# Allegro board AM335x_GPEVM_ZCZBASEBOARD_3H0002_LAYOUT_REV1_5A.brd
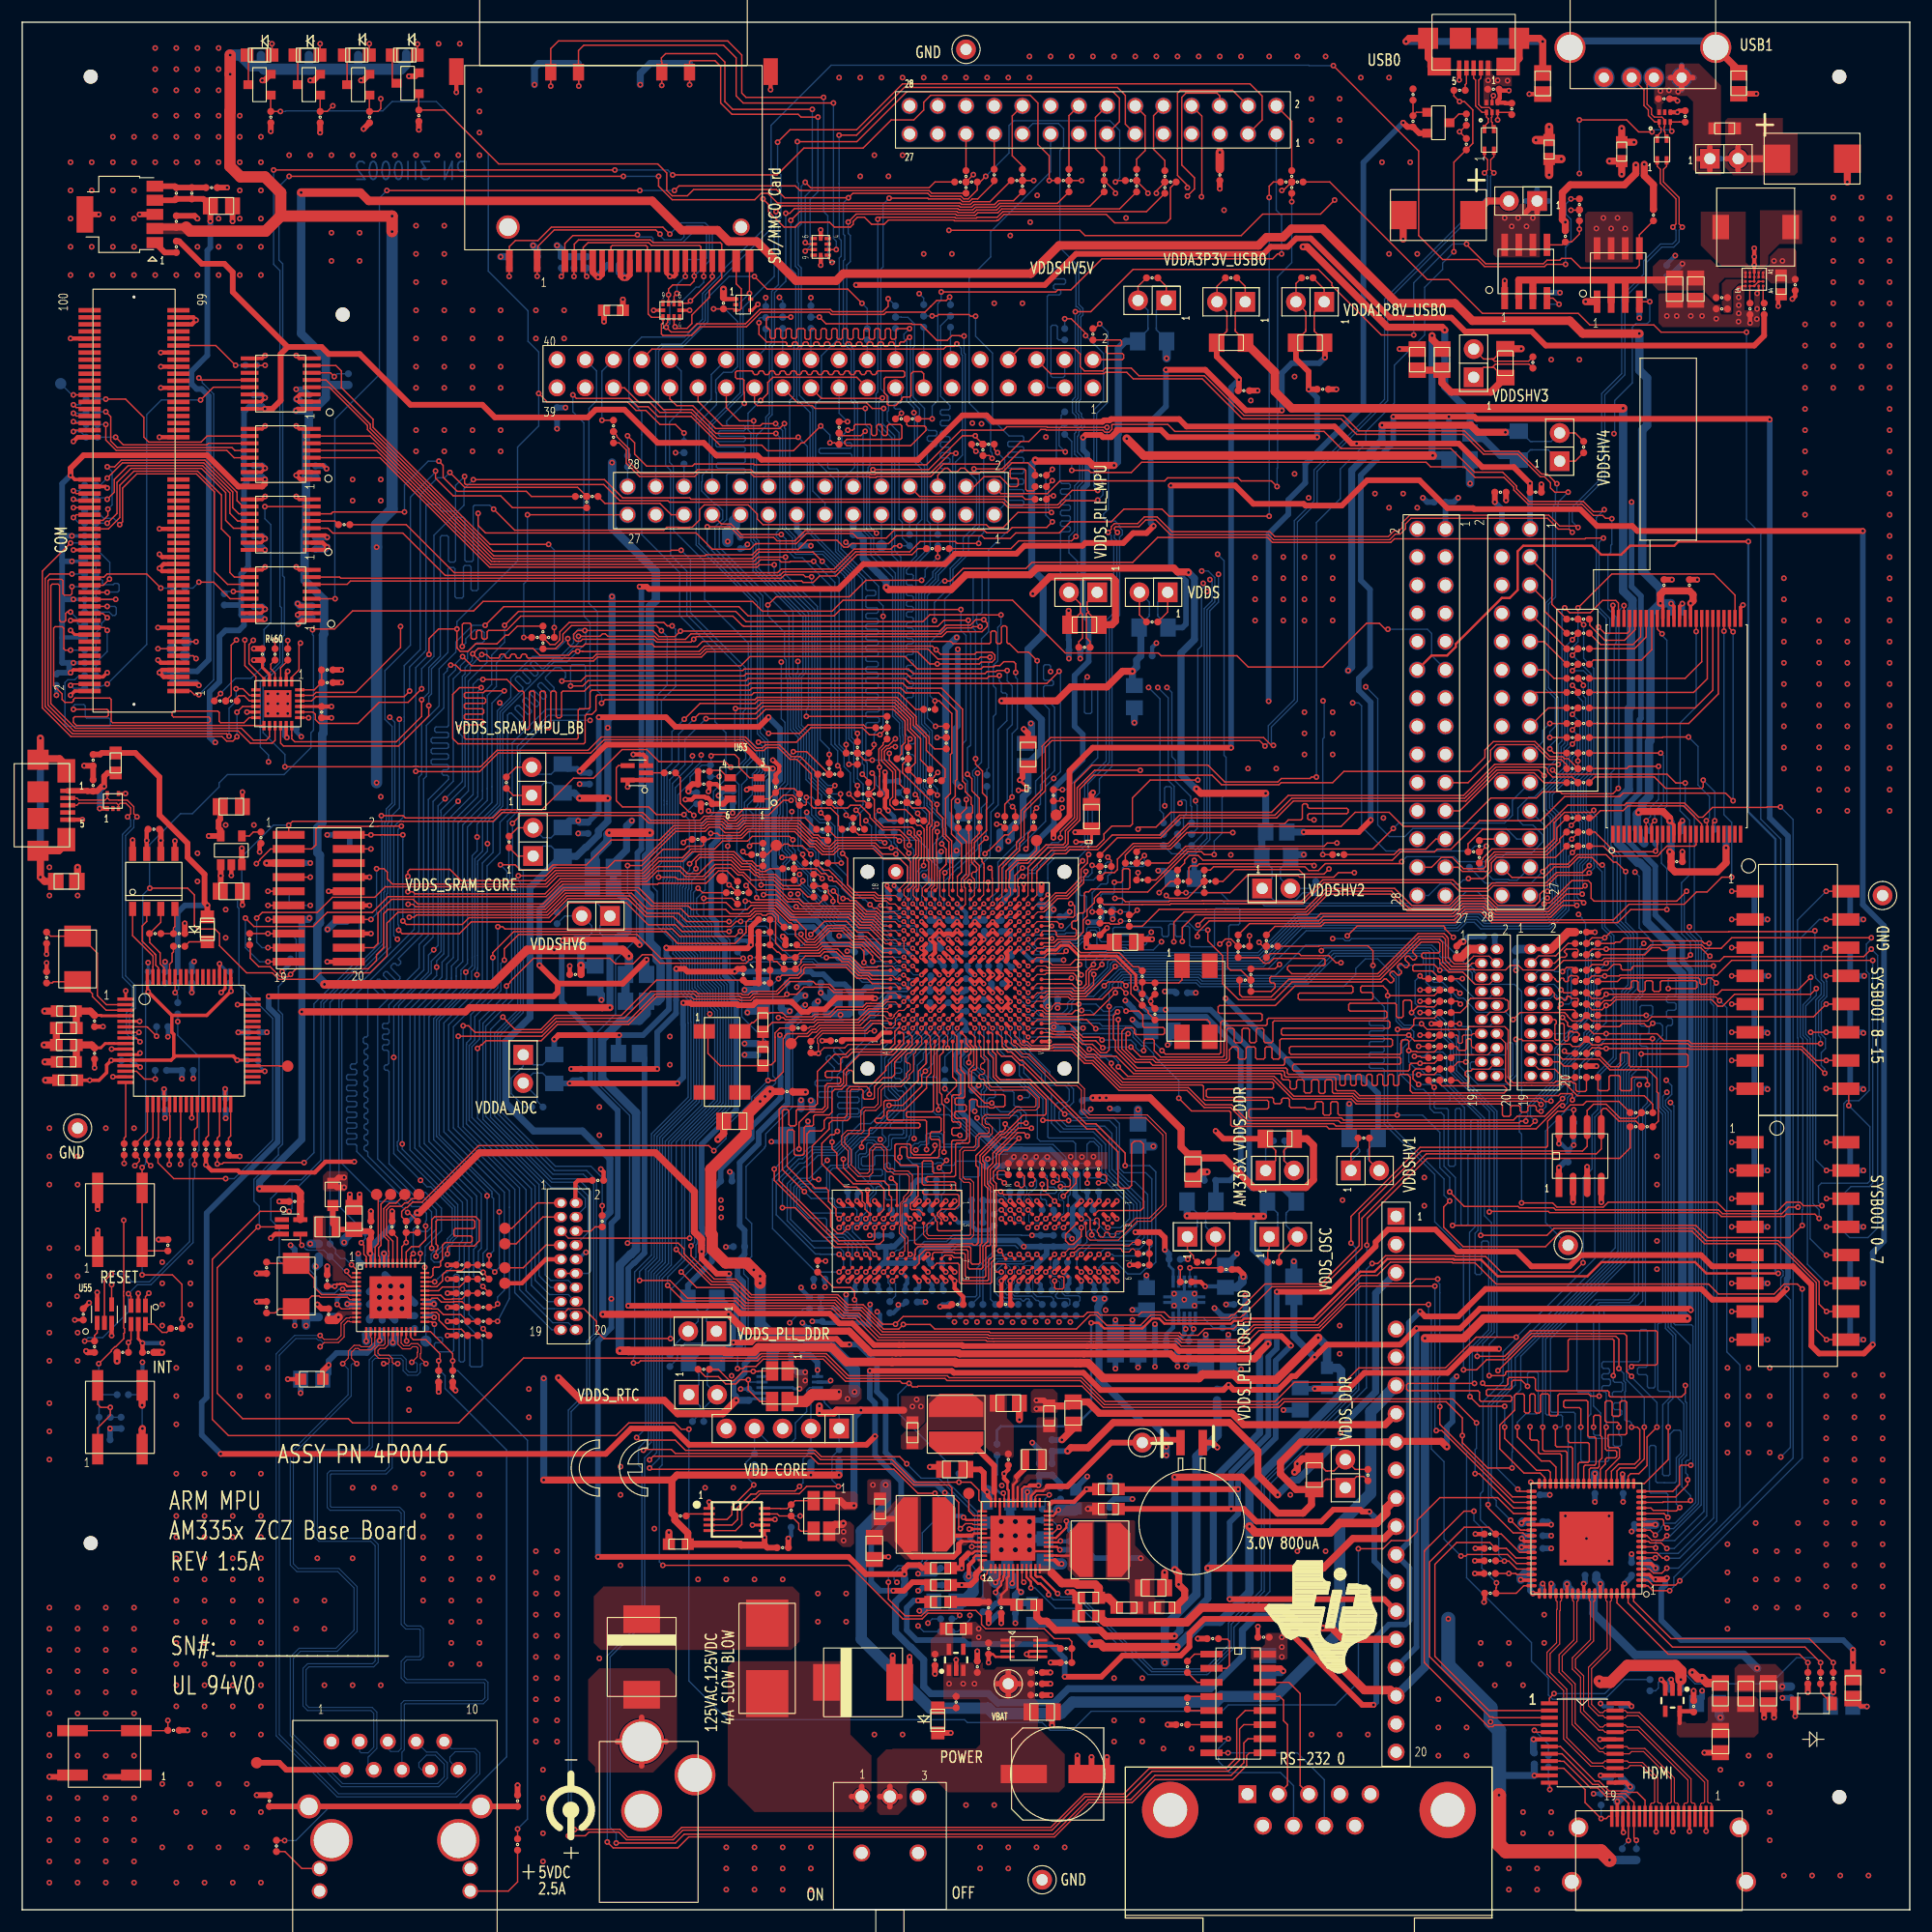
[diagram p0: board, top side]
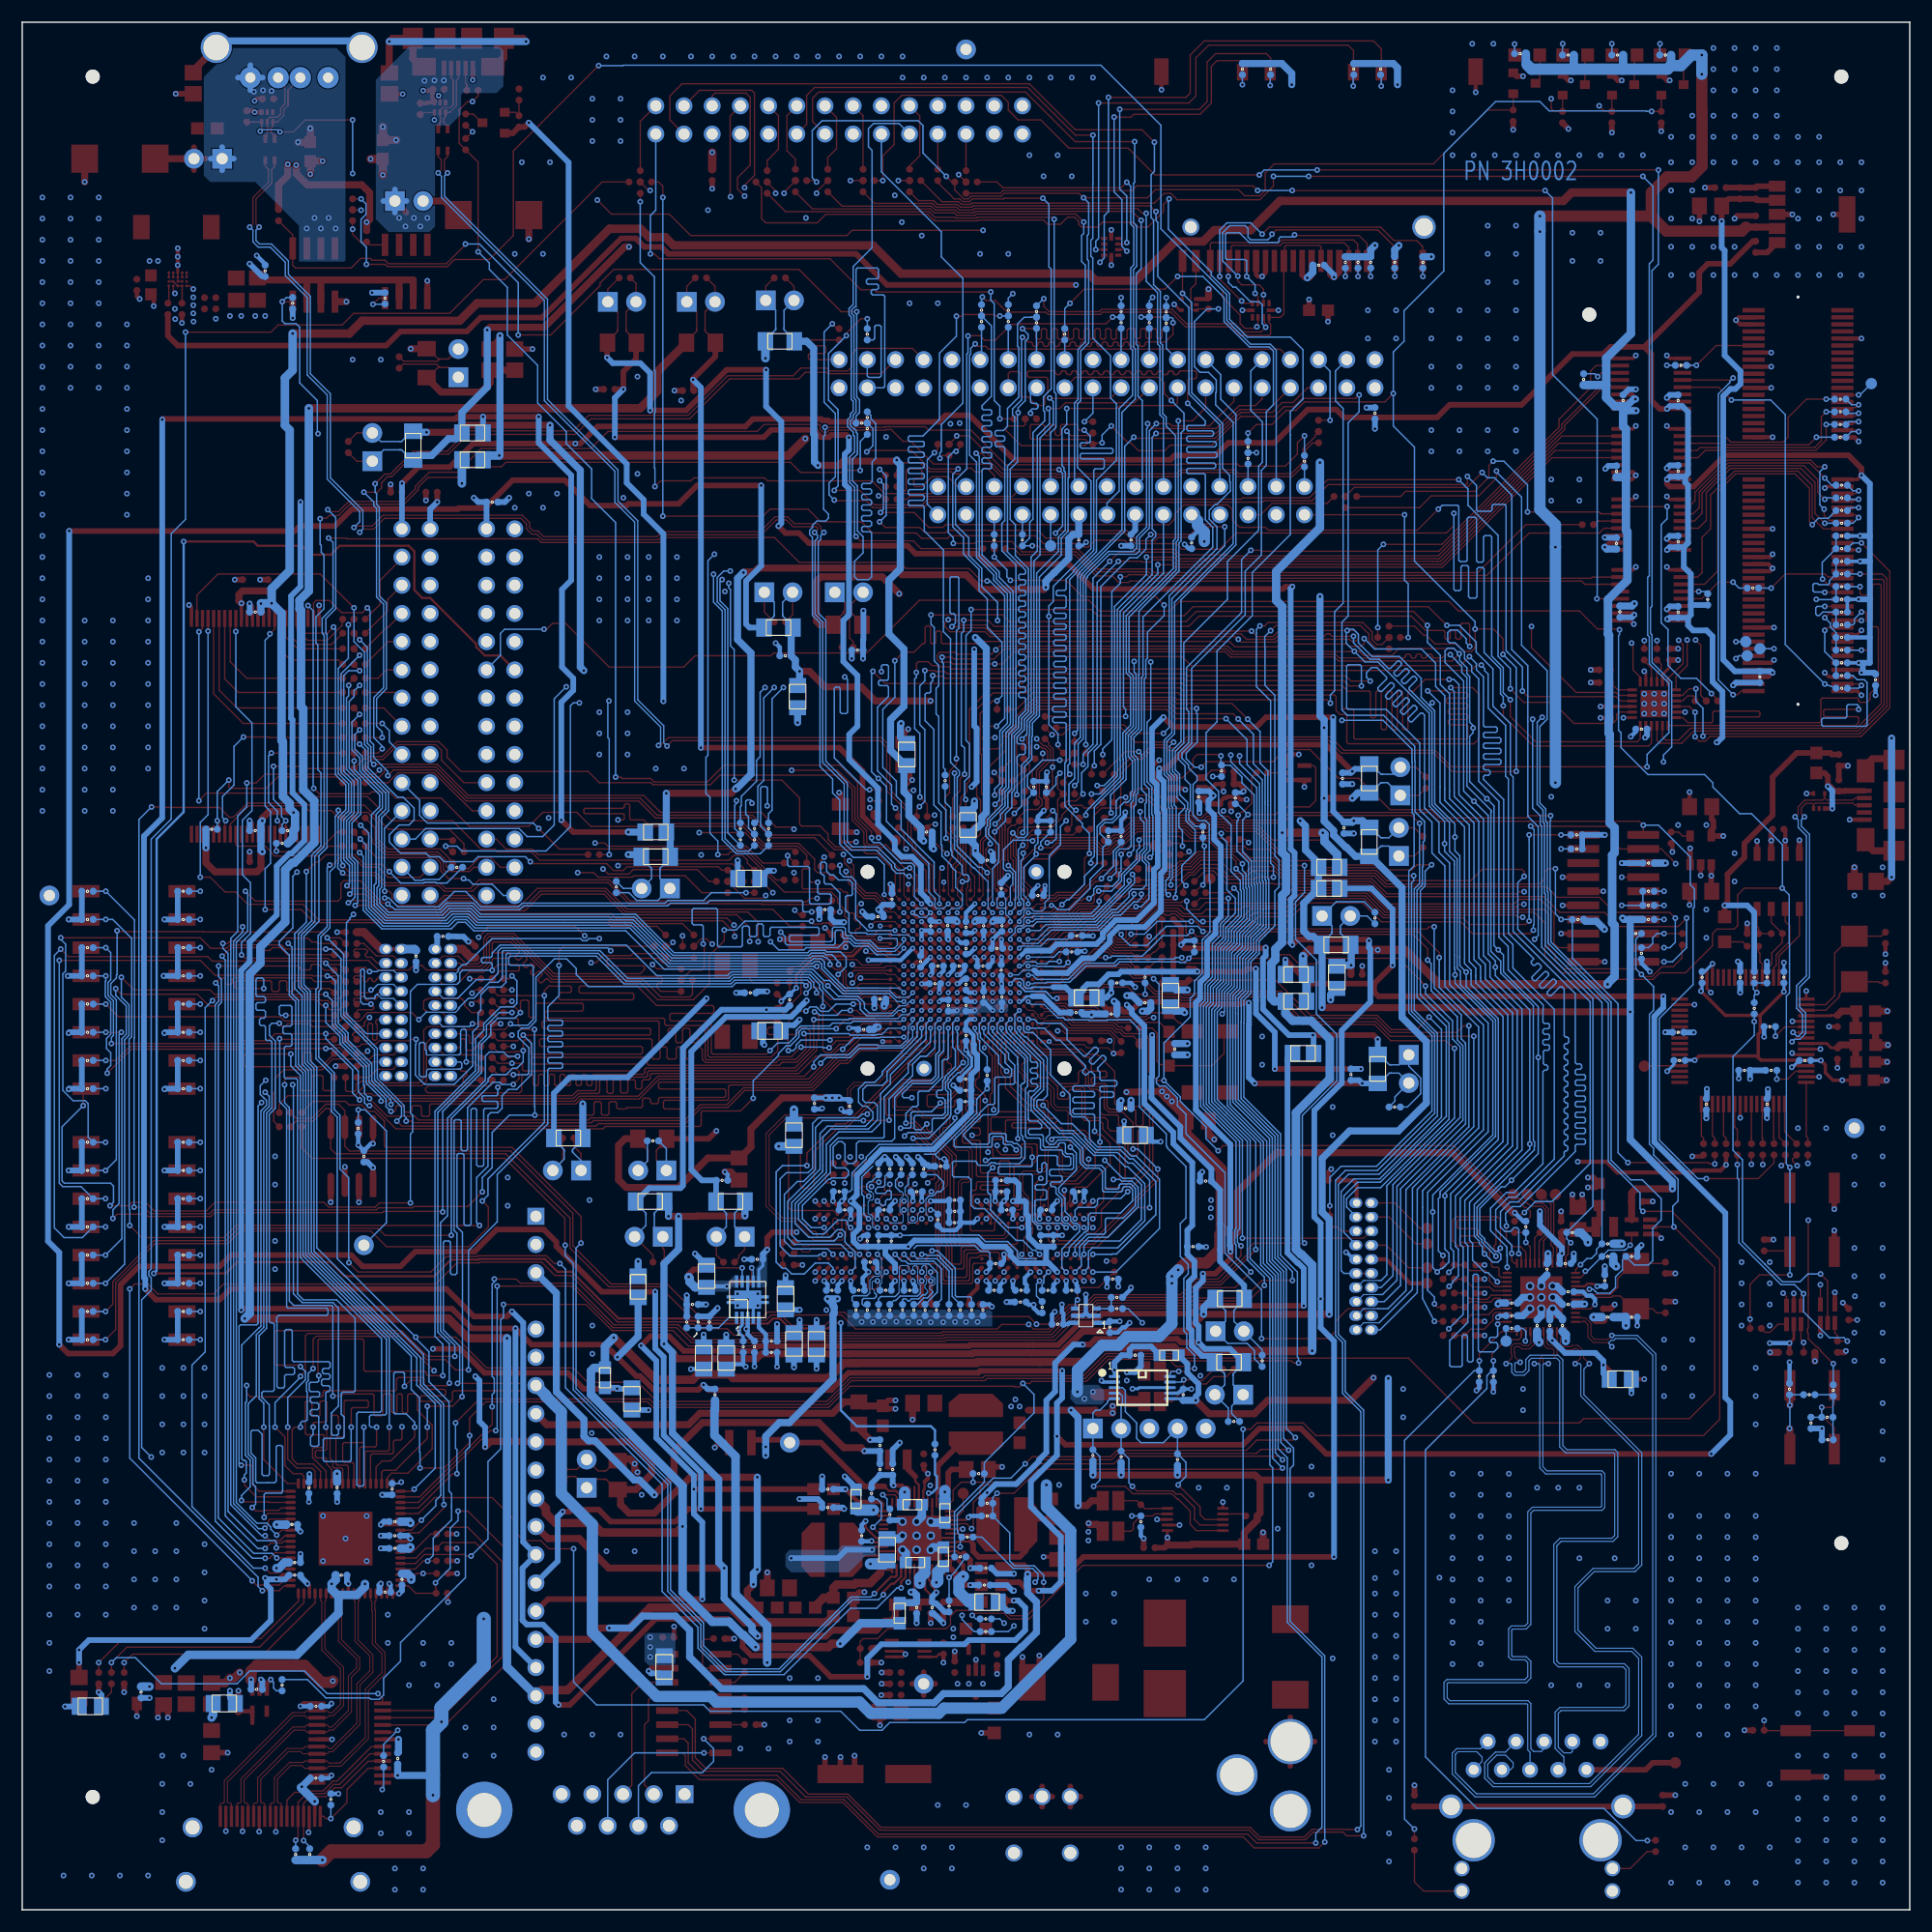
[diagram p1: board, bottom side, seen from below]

Outline 170 x 170 mm; copper layers: TOP, LY2_GND, LY3, LY4, LY5_GND, BOTTOM. Coordinates in mm from the lower left corner of the outline.
Outline path: 0,170 170,170 170,0 0,0 0,170

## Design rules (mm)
net group DDR_DQS0: nets DDR_DQS0 DDR_DQSN0
net group DDR_DQS1: nets DDR_DQS1 DDR_DQSN1
net group EMU_USB: nets EMU_USB_DM EMU_USB_DP
net group ETHER_D0: nets ETHER_D0N ETHER_D0P
net group ETHER_D1: nets ETHER_D1N ETHER_D1P
net group ETHER_D2: nets ETHER_D2N ETHER_D2P
net group ETHER_D3: nets ETHER_D3N ETHER_D3P
net group JTAG: nets JTAG_TDI JTAG_TDO
net group USB1: nets USB1_DM USB1_DP
net group 54: nets AM335X_LCD_DATA0 AM335X_LCD_DATA1 AM335X_LCD_DATA2 AM335X_LCD_DATA3 AM335X_LCD_DATA4 AM335X_LCD_DATA5 AM335X_LCD_DATA6 AM335X_LCD_DATA7 AM335X_LCD_DATA8 AM335X_LCD_DATA9 AM335X_LCD_DATA10 AM335X_LCD_DATA11 AM335X_LCD_DATA12 AM335X_LCD_DATA13 AM335X_LCD_DATA14 AM335X_LCD_DATA15 HDMI_D0 HDMI_D1 HDMI_D2 HDMI_D3 HDMI_D4 HDMI_D5 HDMI_D6 HDMI_D7 HDMI_D8 HDMI_D9 HDMI_D10 HDMI_D11 HDMI_D12 HDMI_D13 HDMI_D14 HDMI_D15 HDMI_D17 HDMI_D18 HDMI_D19 HDMI_D20 HDMI_D21 HDMI_D22 HDMI_D23 HDMI_DE
net group 69: nets AM335X_GMII1_RXD3 ETH_REFCLK ETH_RXCLK ETH_RXD0 ETH_RXD1 ETH_RXD2 ETH_RXD3 ETH_RXDV ETH_TXCLK ETH_TXD0 ETH_TXD1 ETH_TXD2 ETH_TXD3 ETH_TXEN
net group 78: nets AM335X_GMII1_REFCLK
net group 80: nets AM335X_GPMC_A1 AM335X_GPMC_A2 AM335X_GPMC_A3 AM335X_GPMC_BE1N AM335X_GPMC_CLK AM335X_GPMC_CS3N AM335X_MMC2_CLK AM335X_MMC2_CMD AM335X_MMC2_D0 AM335X_MMC2_D1 AM335X_MMC2_D2 AM335X_MMC2_D3 MMC2_CLK MMC2_CMD MMC2_D0 MMC2_D1 MMC2_D2 MMC2_D3
net group 81: nets EXP_GPMC_BE1N EXP_GPMC_CLK EXP_GPMC_CS3N GPMC_A1 GPMC_A2 GPMC_A3 SDIO_GPMC_A1 SDIO_GPMC_A2 SDIO_GPMC_A3 SDIO_GPMC_BE1N SDIO_GPMC_CLK SDIO_GPMC_CS3N
net group DLP-RGB: nets HDMI_HSYNC HDMI_PCLK HDMI_VSYNC
net group EXP_MMC0: nets EXP_MMC0_CLK EXP_MMC0_CMD EXP_MMC0_DAT0 EXP_MMC0_DAT1 EXP_MMC0_DAT2 EXP_MMC0_DAT3
net group H_SDMMC2: nets EXP_MMC1_CLK EXP_MMC1_CMD EXP_MMC1_DAT0 EXP_MMC1_DAT1 EXP_MMC1_DAT2 EXP_MMC1_DAT3 EXP_MMC1_DAT4 EXP_MMC1_DAT5 EXP_MMC1_DAT6 EXP_MMC1_DAT7
net group POWER_TRACE: nets VDDSHV1
net group SD_MMC_CC: nets MMC_CLK MMC_CMD MMC_D0 MMC_D1 MMC_D2 MMC_D3 MMC_D4 MMC_D5 MMC_D6 MMC_D7
net group USB: nets USB0_CONN_DM USB0_CONN_DP USB0_DM USB0_DP USB1_CONN_DM USB1_CONN_DP
nets with their own width: min track width 0.381; nets VDDSHV4 VDDSHV6
nets with their own width: min track width 0.508; nets VDDR_VTT

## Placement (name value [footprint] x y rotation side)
BT1  CoinBattery3.1V  [MS920SE-FL27E]  105.32 42.07 90 top
C1  0.01uF  [SM-7351-CAP-0402]  64.05 100.24 270 bottom
C2  25pF  [SM-7351-CAP-0603]  66.71 79.92 90 top
C3  25pF  [SM-7351-CAP-0603]  66.71 76.87 270 top
C4  18pF  [SM-7351-CAP-0402]  102.02 80.66 90 top
C5  18pF  [SM-7351-CAP-0402]  102.02 82.97 270 top
C6  0.01uF  [SM-7351-CAP-0402]  61.38 101.38 180 top
C7  0.01uF  [SM-7351-CAP-0402]  61.38 102.53 180 top
C8  0.01uF  [SM-7351-CAP-0402]  61.63 99.61 180 top
C9  0.1uF  [SM-7351-CAP-0402]  68.62 85.25 270 top
C10  0.001uF  [SM-7351-CAP-0402]  69.63 85.25 270 top
C11  0.1uF  [SM-7351-CAP-0402]  66.84 86.91 180 top
C12  0.001uF  [SM-7351-CAP-0402]  66.84 88.05 180 top
C13  0.1uF  [SM-7351-CAP-0402]  66.84 84.62 180 top
C14  0.001uF  [SM-7351-CAP-0402]  66.84 85.76 180 top
C15  0.01uF  [SM-7351-CAP-0402]  26.96 107.86 270 top
C16  0.01uF  [SM-7351-CAP-0402]  66.2 77.51 90 bottom
C17  0.01uF  [SM-7351-CAP-0402]  68.87 73.7 0 top
C18  0.01uF  [SM-7351-CAP-0402]  76.75 52.74 0 bottom
C19  0.01uF  [SM-7351-CAP-0402]  83.48 85 0 bottom
C20  0.01uF  [SM-7351-CAP-0402]  72.05 52.49 270 bottom
C23  0.01uF  [SM-7351-CAP-0402]  70.65 72.17 0 bottom
C24  0.01uF  [SM-7351-CAP-0402]  85 83.35 270 bottom
C25  0.01uF  [SM-7351-CAP-0402]  92.75 82.02 0 bottom
C27  0.01uF  [SM-7351-CAP-0402]  81.76 88.62 270 bottom
C28  0.01uF  [SM-7351-CAP-0402]  49.82 84.24 180 top
C29  0.01uF  [SM-7351-CAP-0402]  94.21 79.29 0 bottom
C30  0.01uF  [SM-7351-CAP-0402]  71.41 83.48 0 bottom
C31  0.01uF  [SM-7351-CAP-0402]  87.79 83.41 180 bottom
C32  0.01uF  [SM-7351-CAP-0402]  104.43 82.59 0 bottom
C34  0.01uF  [SM-7351-CAP-0402]  85 86.59 270 bottom
C35  0.01uF  [SM-7351-CAP-0402]  85.64 85 180 bottom
C36  0.01uF  [SM-7351-CAP-0402]  87.54 85 180 bottom
C41  0.01uF  [SM-7351-CAP-0402]  82.21 86.59 0 bottom
C42  0.01uF  [SM-7351-CAP-0402]  83.41 88.62 270 bottom
C43  0.01uF  [SM-7351-CAP-0402]  83.1 94.53 180 bottom
C45  0.01uF  [SM-7351-CAP-0402]  88.56 97.07 180 bottom
C46  0.01uF  [SM-7351-CAP-0402]  86.65 88.63 270 bottom
C47  0.01uF  [SM-7351-CAP-0402]  78.52 91.35 180 bottom
C48  0.01uF  [SM-7351-CAP-0402]  91.67 91.03 90 bottom
C50  0.01uF  [SM-7351-CAP-0402]  92.94 89.45 0 bottom
C52  0.01uF  [SM-7351-CAP-0402]  68.87 81.7 180 bottom
C53  0.01uF  [SM-7351-CAP-0402]  81.83 84.62 270 bottom
C56  0.01uF  [SM-7351-CAP-0402]  71.92 80.68 0 bottom
C60  1uF  [SM-7351-CAP-0402]  69.25 86.91 180 top
C61  0.01uF  [SM-7351-CAP-0402]  117.13 136.94 0 top
C62  0.01uF  [SM-7351-CAP-0402]  110.02 136.82 0 top
C63  0.01uF  [SM-7351-CAP-0402]  50.33 75.22 90 bottom
C64  0.01uF  [SM-7351-CAP-0402]  106.97 65.7 180 bottom
C65  1uF  [SM-7351-CAP-0402]  75.09 80.81 180 bottom
C66  0.01uF  [SM-7351-CAP-0402]  64.55 59.73 180 bottom
C67  0.01uF  [SM-7351-CAP-0402]  100.88 81.95 90 bottom
C68  0.01uF  [SM-7351-CAP-0402]  51.09 101.89 270 bottom
C69  0.01uF  [SM-7351-CAP-0402]  50.96 97.45 270 bottom
C70  0.01uF  [SM-7351-CAP-0402]  94.78 113.45 0 bottom
C71  1uF  [SM-7351-CAP-0402]  75.03 87.73 180 bottom
C72  1uF  [SM-7351-CAP-0402]  75.48 86.27 180 bottom
C73  0.01uF  [SM-7351-CAP-0402]  63.41 65.63 0 bottom
C74  0.01uF  [SM-7351-CAP-0402]  21.63 113.07 90 top
C76  0.01uF  [SM-7351-CAP-0402]  83.41 82.21 90 bottom
C77  0.01uF  [SM-7351-CAP-0402]  81.76 82.21 90 bottom
C78  0.01uF  [SM-7351-CAP-0402]  86.59 81.44 90 bottom
C79  0.01uF  [SM-7351-CAP-0402]  85 81.44 90 bottom
C80  0.01uF  [SM-7351-CAP-0402]  95.48 72.36 270 bottom
C82  0.01uF  [SM-7351-CAP-0402]  98.65 72.62 270 bottom
C83  0.01uF  [SM-7351-CAP-0402]  85 88.49 90 bottom
C84  100uF  [SM-7351-CAP-SMDCAN]  93.26 12.23 180 top
C85  0.1uF  [SM-7351-CAP-0402]  91.35 20.36 0 top
C86  0.1uF  [SM-7351-CAP-0402]  91.35 21.37 0 top
C87  0.01uF  [SM-7351-CAP-0402]  24.17 106.34 0 bottom
C88  1uF  [SM-7351-CAP-0402]  91.35 19.34 0 top
C89  0.01uF  [SM-7351-CAP-0402]  101.26 112.94 0 bottom
C90  0.01uF  [SM-7351-CAP-0402]  89.09 85.41 270 bottom
C91  2.2uF  [SM-7351-CAP-0402]  92.75 41.82 90 bottom
C92  0.01uF  [SM-7351-CAP-0402]  96.56 87.79 0 top
C93  0.01uF  [SM-7351-CAP-0402]  97.7 90.08 0 bottom
C94  0.01uF  [SM-7351-CAP-0402]  88.18 88.61 90 bottom
C96  0.01uF  [SM-7351-CAP-0402]  81.83 91.99 90 bottom
C97  2.2uF  [SM-7351-CAP-0402]  91.6 39.66 90 bottom
C98  0.01uF  [SM-7351-CAP-0402]  94.4 33.69 270 bottom
C101  2.2uF  [SM-7351-CAP-0402]  97.45 36.23 0 bottom
C102  2.2uF  [SM-7351-CAP-0402]  97.45 37.88 0 bottom
C103  2.2uF  [SM-7351-CAP-0402]  88.18 27.22 270 top
C104  2.2uF  [SM-7351-CAP-0402]  89.45 27.22 270 bottom
C107  2.2uF  [SM-7351-CAP-0402]  87.03 27.22 270 top
C108  2.2uF  [SM-7351-CAP-0402]  88.05 27.22 270 bottom
C109  2.2uF  [SM-7351-CAP-0402]  83.22 30.77 180 bottom
C110  2.2uF  [SM-7351-CAP-0402]  83.35 29.25 180 bottom
C111  0.01uF  [SM-7351-CAP-0402]  87.03 23.53 270 top
C112  1uF  [SM-7351-CAP-0402]  86.02 21.88 90 top
C113  1uF  [SM-7351-CAP-0402]  82.21 22.52 270 top
C114  0.01uF  [SM-7351-CAP-0402]  94.02 22.26 180 top
C115  0.01uF  [SM-7351-CAP-0402]  23.53 94.27 0 bottom
C116  0.01uF  [SM-7351-CAP-0402]  139.23 67.86 270 bottom
C117  1uF  [SM-7351-CAP-0402]  13.12 59.85 90 top
C118  1uF  [SM-7351-CAP-0402]  7.4 42.33 0 bottom
C125  0.01uF  [SM-7351-CAP-0402]  80.1 54.74 0 bottom
C126  0.01uF  [SM-7351-CAP-0402]  82.33 58.2 0 bottom
C127  0.1uF  [SM-7351-CAP-0402]  149.01 97.19 0 bottom
C128  0.01uF  [SM-7351-CAP-0402]  149.01 94.4 0 top
C129  0.01uF  [SM-7351-CAP-0402]  149.01 116.88 0 bottom
C130  0.01uF  [SM-7351-CAP-0402]  150.15 119.29 90 top
C131  0.1uF  [SM-7351-CAP-0402]  147.87 119.29 90 top
C132  0.1uF  [SM-7351-CAP-0402]  133.13 127.67 0 top
C133  0.1uF  [SM-7351-CAP-0402]  136.31 127.67 0 top
C134  0.1uF  [SM-7351-CAP-0402]  70.14 123.35 270 bottom
C135  0.1uF  [SM-7351-CAP-0402]  48.17 134.78 270 bottom
C136  0.01uF  [SM-7351-CAP-0402]  134.53 85.89 270 bottom
C137  0.01uF  [SM-7351-CAP-0402]  140.37 88.05 0 top
C138  0.01uF  [SM-7351-CAP-0402]  132.12 87.67 180 bottom
C139  0.01uF  [SM-7351-CAP-0402]  129.2 86.27 90 top
C140  0.01uF  [SM-7351-CAP-0402]  51.85 65.7 0 top
C141  0.1uF  [SM-7351-CAP-0402]  64.68 123.1 270 bottom
C142  0.1uF  [SM-7351-CAP-0402]  145.71 34.71 180 bottom
C143  0.1uF  [SM-7351-CAP-0402]  145.45 31.28 180 bottom
C144  0.1uF  [SM-7351-CAP-0402]  141.64 38.01 270 bottom
C145  0.1uF  [SM-7351-CAP-0402]  136.44 34.96 0 bottom
C146  0.1uF  [SM-7351-CAP-0402]  136.44 32.55 0 bottom
C147  0.1uF  [SM-7351-CAP-0402]  135.8 29.76 270 bottom
C148  0.1uF  [SM-7351-CAP-0402]  74.84 123.35 270 bottom
C149  0.01uF  [SM-7351-CAP-0402]  143.55 18.33 180 bottom
C150  0.1uF  [SM-7351-CAP-0402]  136.44 33.69 0 bottom
C151  0.1uF  [SM-7351-CAP-0402]  145.45 30.14 180 bottom
C152  0.1uF  [SM-7351-CAP-0402]  144.18 38.01 270 bottom
C153  0.1uF  [SM-7351-CAP-0402]  159.3 19.6 270 bottom
C154  0.1uF  [SM-7351-CAP-0402]  141.26 30.14 180 bottom
C155  0.01uF  [SM-7351-CAP-0402]  82.46 55.79 180 bottom
C156  0.01uF  [SM-7351-CAP-0402]  95.92 63.03 0 bottom
C157  0.01uF  [SM-7351-CAP-0402]  136.18 13.63 90 bottom
C158  0.01uF  [SM-7351-CAP-0402]  143.55 11.85 180 bottom
C159  1uF  [SM-7351-CAP-0402]  150.53 18.33 90 top
C160  1uF  [SM-7351-CAP-0402]  148.88 19.85 180 bottom
C161  0.01uF  [SM-7351-CAP-0402]  13.5 111.04 270 bottom
C162  0.01uF  [SM-7351-CAP-0402]  3.09 110.78 270 bottom
C163  0.01uF  [SM-7351-CAP-0402]  26.11 116.91 270 bottom
C164  0.01uF  [SM-7351-CAP-0402]  20.87 116.88 90 bottom
C165  0.01uF  [SM-7351-CAP-0402]  26.42 123.06 90 bottom
C166  0.01uF  [SM-7351-CAP-0402]  20.87 123.23 90 bottom
C167  0.01uF  [SM-7351-CAP-0402]  25.82 135.93 90 bottom
C168  0.01uF  [SM-7351-CAP-0402]  20.87 135.93 90 bottom
C169  0.01uF  [SM-7351-CAP-0402]  26.42 129.54 90 bottom
C170  0.01uF  [SM-7351-CAP-0402]  20.87 129.58 90 bottom
C171  15pF  [SM-7351-CAP-0402]  15.28 154.6 90 top
C172  2.2uF  [SM-7351-CAP-0805]  17.94 153.45 0 top
C173  1uF  [SM-7351-CAP-0402]  13.88 152.06 90 top
C174  0.01uF  [SM-7351-CAP-0402]  90.08 55.79 180 bottom
C175  0.01uF  [SM-7351-CAP-0402]  111.8 24.55 180 top
C176  0.1uF  [SM-7351-CAP-0402]  104.94 21.88 270 top
C177  0.1uF  [SM-7351-CAP-0402]  107.23 24.42 180 top
C178  0.1uF  [SM-7351-CAP-0402]  104.94 18.58 270 top
C179  0.1uF  [SM-7351-CAP-0402]  104.43 16.67 180 top
C180  0.1uF  [SM-7351-CAP-0402]  53.25 148.12 180 bottom
C181  0.01uF  [SM-7351-CAP-0402]  97.07 55.79 180 bottom
C182  150uF  [SM-7351-CAP-2917]  127.55 152.63 0 top
C183  0.01uF  [SM-7351-CAP-0402]  132.5 163.97 0 top
C184  2.2uF  [SM-7351-CAP-0402]  148.12 147.61 90 bottom
C185  150uF  [SM-7351-CAP-2917]  161.2 157.71 180 top
C186  0.01uF  [SM-7351-CAP-0402]  147.87 163.11 0 top
C187  0.1uF  [SM-7351-CAP-0402]  159.68 146.34 270 top
C188  0.01uF  [SM-7351-CAP-0402]  93.64 58.33 0 bottom
C189  0.01uF  [SM-7351-CAP-0402]  94.65 55.79 180 bottom
C190  0.1uF  [SM-7351-CAP-0402]  27.47 56.68 90 bottom
C191  1uF  [SM-7351-CAP-0402]  27.47 56.68 90 top
C192  1uF  [SM-7351-CAP-0402]  27.6 53.63 90 top
C193  0.1uF  [SM-7351-CAP-0402]  35.85 54.65 180 bottom
C194  0.1uF  [SM-7351-CAP-0402]  32.42 52.62 90 bottom
C195  0.01uF  [SM-7351-CAP-0402]  96.43 64.68 180 bottom
C196  0.1uF  [SM-7351-CAP-0402]  31.03 58.2 180 bottom
C197  0.1uF  [SM-7351-CAP-0402]  31.41 61.51 90 top
C198  0.1uF  [SM-7351-CAP-0402]  32.68 57.7 270 bottom
C199  0.1uF  [SM-7351-CAP-0402]  30.77 54.52 0 bottom
C200  0.1uF  [SM-7351-CAP-0402]  31.28 52.62 90 bottom
C201  0.1uF  [SM-7351-CAP-0402]  33.57 52.62 90 bottom
C202  0.01uF  [SM-7351-CAP-0402]  89.45 64.68 0 bottom
C203  0.01uF  [SM-7351-CAP-0402]  71.79 56.81 180 bottom
C204  22pF  [SM-7351-CAP-0402]  22.01 54.27 270 top
C205  470pF  [SM-7351-CAP-0402]  37.5 48.04 270 top
C206  470pF  [SM-7351-CAP-0402]  38.77 48.04 270 top
C207  470pF  [SM-7351-CAP-0402]  35.85 53.5 180 bottom
C208  0.01uF  [SM-7351-CAP-0402]  86.02 61.89 0 bottom
C209  0.1uF  [SM-7351-CAP-0402]  127.67 126.78 180 bottom
C212  22pF  [SM-7351-CAP-0402]  22.01 57.82 90 top
C213  0.01uF  [SM-7351-CAP-0402]  24.55 63.79 180 top
C214  0.01uF  [SM-7351-CAP-0402]  107.86 156.25 270 top
C215  0.01uF  [SM-7351-CAP-0402]  65.44 46.39 90 bottom
C216  0.01uF  [SM-7351-CAP-0402]  77.76 63.03 180 bottom
C217  0.01uF  [SM-7351-CAP-0402]  81.83 64.68 180 bottom
C218  0.01uF  [SM-7351-CAP-0402]  74.84 64.68 0 bottom
C219  0.01uF  [SM-7351-CAP-0402]  92.37 63.03 180 bottom
C220  0.01uF  [SM-7351-CAP-0402]  75.48 55.79 180 bottom
C221  0.01uF  [SM-7351-CAP-0402]  81.32 63.03 0 bottom
C222  0.01uF  [SM-7351-CAP-0402]  68.49 32.61 0 top
C223  0.01uF  [SM-7351-CAP-0402]  80.05 55.79 180 bottom
C224  0.01uF  [SM-7351-CAP-0402]  86.02 62.9 0 bottom
C225  0.01uF  [SM-7351-CAP-0402]  86.02 63.92 0 bottom
C226  0.01uF  [SM-7351-CAP-0402]  84.24 54.52 180 top
C227  0.01uF  [SM-7351-CAP-0402]  88.56 54.52 180 top
C232  10uF  [SM-7351-CAP-0805]  64.17 71.03 180 top
C233  10uF  [SM-7351-CAP-0805]  105.45 66.71 270 top
C234  10uF  [SM-7351-CAP-0805]  91.86 17.82 0 top
C235  10uF  [SM-7351-CAP-0805]  94.65 44.74 270 top
C236  10uF  [SM-7351-CAP-0805]  83.1 27.72 180 bottom
C237  10uF  [SM-7351-CAP-0805]  88.81 45.63 0 top
C238  10uF  [SM-7351-CAP-0805]  83.98 39.66 180 top
C239  10uF  [SM-7351-CAP-0805]  76.75 32.55 270 top
C240  10uF  [SM-7351-CAP-0805]  92.11 32.42 90 bottom
C241  10uF  [SM-7351-CAP-0805]  101.89 28.99 0 top
C242  10uF  [SM-7351-CAP-0805]  151.8 18.58 180 bottom
C243  10uF  [SM-7351-CAP-0805]  163.87 18.33 180 bottom
C244  10uF  [SM-7351-CAP-0805]  157.26 19.47 270 top
C245  10uF  [SM-7351-CAP-0805]  112.18 21.88 270 bottom
C246  10uF  [SM-7351-CAP-0805]  66.59 82.33 90 bottom
C247  10uF  [SM-7351-CAP-0805]  51.6 83.98 270 bottom
C248  10uF  [SM-7351-CAP-0805]  26.07 47.79 180 bottom
C249  10uF  [SM-7351-CAP-0805]  100.16 109.26 270 bottom
C250  4.7uF  [SM-7351-CAP-0603]  89.83 36.49 180 bottom
C251  4.7uF  [SM-7351-CAP-0603]  94.91 36.99 90 bottom
C252  4.7uF  [SM-7351-CAP-0603]  89.57 31.28 0 bottom
C253  4.7uF  [SM-7351-CAP-0603]  86.91 35.72 270 bottom
C254  4.7uF  [SM-7351-CAP-0603]  87.03 31.79 90 bottom
C255  4.7uF  [SM-7351-CAP-0603]  53.25 144.06 180 top
C256  10uF  [SM-7351-CAP-0805]  29.88 62.27 90 top
C257  10uF  [SM-7351-CAP-0805]  90.33 104.05 90 bottom
C258  10uF  [SM-7351-CAP-0805]  102.65 79.16 0 bottom
C259  10uF  [SM-7351-CAP-0805]  99.35 87.16 0 top
C260  0.1uF  [SM-7351-CAP-0402]  24.17 86.14 270 bottom
C261  10uF  [SM-7351-CAP-0805]  115.1 46.01 270 bottom
C262  4.7uF  [SM-7351-CAP-0603]  137.51 158.53 270 top
C263  4.7uF  [SM-7351-CAP-0603]  158.41 146.34 270 top
C264  0.1uF  [SM-7351-CAP-0402]  155.61 144.18 270 top
C265  4.7uF  [SM-7351-CAP-0603]  144.06 158.34 270 top
C266  10uF  [SM-7351-CAP-0805]  108.37 57.06 90 bottom
C267  22uF  [SM-7351-CAP-0805]  69.76 69.76 0 bottom
C268  22uF  [SM-7351-CAP-0805]  152.95 15.15 270 top
C269  22uF  [SM-7351-CAP-0805]  150.72 145.96 270 top
C270  22uF  [SM-7351-CAP-0805]  148.82 145.96 270 top
C271  0.1uF  [SM-7351-CAP-0402]  44.61 9.82 270 top
C272  0.1uF  [SM-7351-CAP-0402]  22.26 9.82 270 top
C273  10uF  [SM-7351-CAP-0805]  104.56 92.87 0 bottom
C274  10uF  [SM-7351-CAP-0805]  84.82 97.7 90 bottom
C275  10uF  [SM-7351-CAP-0805]  101.26 55.03 90 bottom
C276  10uF  [SM-7351-CAP-0805]  98.46 50.96 270 bottom
C277  10uF  [SM-7351-CAP-0805]  100.49 50.96 270 bottom
C278  10uF  [SM-7351-CAP-0805]  108.62 49.69 270 bottom
C279  10uF  [SM-7351-CAP-0805]  106.59 49.69 270 bottom
C280  22uF  [SM-7351-CAP-0805]  100.49 69.76 90 bottom
C303  0.1uF  [SM-7351-CAP-0402]  85.05 74.81 0 bottom
C304  0.1uF  [SM-7351-CAP-0402]  78.27 60.24 90 bottom
C305  0.1uF  [SM-7351-CAP-0402]  77.13 60.24 90 bottom
C306  0.1uF  [SM-7351-CAP-0402]  91.73 60.24 90 bottom
C307  0.1uF  [SM-7351-CAP-0402]  92.87 60.24 90 bottom
C308  0.1uF  [SM-7351-CAP-0402]  103.8 58.58 0 bottom
C309  0.1uF  [SM-7351-CAP-0402]  85.05 73.8 180 bottom
C311  2.2uF  [SM-7351-CAP-0805]  18.83 99.35 0 top
C312  10uF  [SM-7351-CAP-0805]  18.83 91.73 0 top
C313  0.01uF  [SM-7351-CAP-0402]  21.5 96.56 270 top
C314  0.01uF  [SM-7351-CAP-0402]  6.39 101.26 90 top
C315  0.01uF  [SM-7351-CAP-0402]  6.39 103.54 270 top
C316  0.01uF  [SM-7351-CAP-0402]  18.71 83.98 90 bottom
C317  0.01uF  [SM-7351-CAP-0402]  12.86 72.55 270 bottom
C318  0.01uF  [SM-7351-CAP-0402]  5.5 53.63 90 top
C319  0.01uF  [SM-7351-CAP-0402]  11.34 50.2 180 top
C320  4.7uF  [SM-7351-CAP-0603]  3.97 80.94 0 top
C321  0.01uF  [SM-7351-CAP-0402]  11.34 83.98 90 bottom
C322  0.01uF  [SM-7351-CAP-0402]  18.33 72.55 270 bottom
C323  0.01uF  [SM-7351-CAP-0402]  6.51 80.05 90 top
C324  0.01uF  [SM-7351-CAP-0402]  20.74 76.49 0 bottom
C325  0.01uF  [SM-7351-CAP-0402]  20.87 79.03 0 bottom
C326  4.7uF  [SM-7351-CAP-0603]  3.97 76.36 0 top
C327  0.01uF  [SM-7351-CAP-0402]  9.44 76.49 0 bottom
C328  0.01uF  [SM-7351-CAP-0402]  15.28 83.98 90 bottom
C329  0.01uF  [SM-7351-CAP-0402]  6.51 77.13 90 top
C330  4.7uF  [SM-7351-CAP-0603]  4.1 74.71 180 top
C331  0.01uF  [SM-7351-CAP-0402]  14.9 75.6 180 bottom
C332  18pF  [SM-7351-CAP-0402]  2.2 87.54 270 top
C333  18pF  [SM-7351-CAP-0402]  2.2 83.98 90 top
C334  0.1uF  [SM-7351-CAP-0402]  11.85 97.32 180 top
C335  0.1uF  [SM-7351-CAP-0402]  81.83 65.7 180 bottom
C336  0.1uF  [SM-7351-CAP-0402]  93.89 60.24 270 bottom
C337  10pF  [SM-7351-CAP-0402]  102.53 50.2 180 bottom
C338  0.1uF  [SM-7351-CAP-0402]  104.05 50.71 270 bottom
C339  0.1uF  [SM-7351-CAP-0402]  105.07 50.71 270 bottom
C340  0.001uF  [SM-7351-CAP-0402]  109.64 54.52 180 bottom
C341  0.001uF  [SM-7351-CAP-0402]  109.13 52.93 90 bottom
C352  0.1uF  [SM-7351-CAP-0402]  101 58.08 180 top
C353  0.1uF  [SM-7351-CAP-0402]  61.38 48.68 180 top
C354  0.1uF  [SM-7351-CAP-0402]  69.76 49.95 0 bottom
C355  0.1uF  [SM-7351-CAP-0402]  95.67 113.7 180 top
C356  0.1uF  [SM-7351-CAP-0402]  69.25 35.98 270 top
C357  0.1uF  [SM-7351-CAP-0402]  69.25 34.96 270 bottom
C358  4.7uF  [SM-7351-CAP-0603]  66.71 49.95 0 bottom
C359  4.7uF  [SM-7351-CAP-0603]  59.09 32.93 180 top
C360  0.1uF  [SM-7351-CAP-0402]  43.85 96.18 90 top
C361  0.1uF  [SM-7351-CAP-0402]  113.19 69.25 0 bottom
C362  0.1uF  [SM-7351-CAP-0402]  43.6 101.51 90 top
C363  0.1uF  [SM-7351-CAP-0402]  120.81 69.51 0 top
C364  0.1uF  [SM-7351-CAP-0402]  115.73 146.98 180 top
C365  0.1uF  [SM-7351-CAP-0402]  140.63 131.74 90 top
C366  0.1uF  [SM-7351-CAP-0402]  108.88 146.98 180 top
C367  0.1uF  [SM-7351-CAP-0402]  101.76 146.98 180 top
C368  0.1uF  [SM-7351-CAP-0402]  58.33 49.44 90 bottom
C369  0.1uF  [SM-7351-CAP-0402]  48.17 89.32 270 bottom
C370  0.1uF  [SM-7351-CAP-0402]  101.76 115.99 180 top
C371  0.1uF  [SM-7351-CAP-0402]  106.34 58.33 0 top
C372  0.1uF  [SM-7351-CAP-0402]  46.39 72.3 0 bottom
C373  0.1uF  [SM-7351-CAP-0402]  112.69 58.33 0 top
C374  0.1uF  [SM-7351-CAP-0402]  116.5 92.11 90 bottom
C375  0.1uF  [SM-7351-CAP-0402]  136.05 139.36 90 top
C376  0.1uF  [SM-7351-CAP-0402]  83.48 54.01 90 bottom
C377  0.1uF  [SM-7351-CAP-0402]  87.29 66.97 180 bottom
C378  0.1uF  [SM-7351-CAP-0402]  121.2 39.15 90 top
C379  0.1uF  [SM-7351-CAP-0402]  60.87 43.98 0 bottom
D1  -  [B520C-13-F]  55.79 22.77 270 top
D2  -  [SMCJ15CA]  75.73 20.48 0 top
D3  Green LED  [SM_LED_0805]  82.46 17.06 270 top
D4  Green LED  [SM_LED_0805]  34.45 167.04 180 top
D5  Green LED  [SM_LED_0805]  30.14 167.04 180 top
D6  Green LED  [SM_LED_0805]  25.69 167.04 180 top
D7  Green LED  [SM_LED_0805]  21.37 167.04 180 top
D8  MMSD103T1  [SOD-123]  161.33 18.58 0 top
D9  GDZT2R5.1  [GMD2_2PIN]  96.05 96.18 90 top
D10  GDZT2R5.1  [GMD2_2PIN]  90.46 101 180 top
D11  Green LED  [SM_LED_0805]  16.67 88.3 270 top
F1  Fuse 4A  [SMDFUSEBLK]  67.09 22.64 270 top
FB1  150OHM800mA  [SM-7351-IND-0805]  55.28 81.83 0 bottom
FB2  150OHM800mA  [SM-7351-IND-0805]  55.28 84.24 0 bottom
FB3  150OHM800mA  [SM-7351-IND-0805]  129.45 130.59 180 bottom
FB4  150OHM800mA  [SM-7351-IND-0805]  129.45 133.01 180 bottom
FB5  150OHM800mA  [SM-7351-IND-0805]  112.94 97.07 0 bottom
FB6  150OHM800mA  [SM-7351-IND-0805]  114.53 56.11 270 bottom
FB7  150OHM800mA  [SM-7351-IND-0805]  52.3 93.89 180 bottom
FB8  150OHM800mA  [SM-7351-IND-0805]  52.3 91.99 180 bottom
FB9  150OHM800mA  [SM-7351-IND-0805]  54.65 77.13 0 bottom
FB10  150OHM800mA  [SM-7351-IND-0805]  74.14 82.14 180 bottom
FB11  150OHM800mA  [SM-7351-IND-0805]  152.95 19.47 270 top
FB12  150OHM800mA  [SM-7351-IND-0805]  164.88 19.98 270 top
FB13  150OHM800mA  [SM-7351-IND-0805]  155.23 19.47 270 top
FB14  150OHM800mA  [SM-7351-IND-0805]  136.94 164.48 90 top
FB15  600mAFB10ohm  [HF70ACB201209]  26.07 47.79 0 top
FB16  600mAFB10ohm  [HF70ACB201209]  27.98 64.43 270 top
FB19  150OHM800mA  [SM-7351-IND-0805]  154.6 164.5 90 top
FB20  150OHM800mA  [SM-7351-IND-0805]  125.64 139.61 90 top
FB21  150OHM800mA  [SM-7351-IND-0805]  127.86 139.61 90 top
FB22  220OHM2A  [SM-7351-IND-0603]  8.42 103.29 90 top
FB23  220OHM2A  [SM-7351-IND-0603]  3.97 79.41 180 top
FB24  220OHM2A  [SM-7351-IND-0603]  3.97 77.89 180 top
FB25  150OHM800mA  [SM-7351-IND-0805]  3.97 92.62 0 top
J1  Power Jack RAPC712  [RAPC712]  55.79 15.15 90 top
J2  CTI JTAG  [HEADER10X2]  26.71 91.1 270 top
J3  Header_14x2  [JUMP2X14-6040-1]  135.8 124.37 90 top
J4  Header_14x2  [JUMP2X14-6040-1]  128.18 124.37 90 top
J5  Header_20x2  [JUMP2X20-6040-1]  96.43 137.07 0 top
J6  Header_14x2  [JUMP2X14-6040-1]  87.54 125.64 0 top
J7  Header_10x2  [HEADER_10X2_TH]  135.93 86.52 270 top
J8  Header_10x2  [HEADER_10X2_TH]  131.48 86.52 270 top
J9  Header_10x2  [HEADER_10X2_TH]  48.55 63.66 270 top
J10  HDMIConnA  [SMD_HDMIA_RA]  147.41 8.42 0 top
J11  MEC6_100pin  [MEC6-150-02-S-D-RA1]  10.07 126.91 90 top
J12  Conn_DB9M_TH  [NORCOMP_DB9M_TH]  110.4 10.41 180 top
J13  MHC-W21-601  [MHC-W21-601-LF]  53.25 148.5 180 top
J14  USB_MicroAB  [ZX62-AB-5PA]  130.72 165.87 180 top
J15  RJ-45 Gigabit  [6605814-6]  27.85 15.15 0 top
J16  Header_14x2  [JUMP2X14-6040-1]  112.94 159.93 0 top
J17  HEADER 5  [HEADER_5X1]  73.57 43.34 180 top
J18  USB A  [USB_STD_A_TH]  149.45 165.01 180 top
J19  Header20x1_wkey  [HEADER20X1_0_100IN]  123.74 62.46 270 top
J20  HEADER 2  [HEADER_2X1]  111.99 66.59 270 top
J21  HEADER 2  [HEADER_2X1]  103.16 118.66 90 top
J22  HEADER 2  [HEADER_2X1]  96.81 118.66 90 top
J23  HEADER 2  [HEADER_2X1]  45.88 100.37 0 top
J24  HEADER 2  [HEADER_2X1]  104.94 60.62 270 top
J25  HEADER 2  [HEADER_2X1]  46.01 94.91 0 top
J26  HEADER 2  [HEADER_2X1]  119.67 66.59 270 top
J27  HEADER 2  [HEADER_2X1]  45.12 77 180 top
J28  HEADER 2  [HEADER_2X1]  117.26 144.82 90 top
J29  HEADER 2  [HEADER_2X1]  112.31 60.62 270 top
J30  HEADER 2  [HEADER_2X1]  138.47 130.47 0 top
J31  HEADER 2  [HEADER_2X1]  110.15 144.82 90 top
J32  HEADER 2  [HEADER_2X1]  103.03 144.94 90 top
J33  HEADER 2  [HEADER_2X1]  62.52 52.11 90 top
J34  HEADER 2  [HEADER_2X1]  52.93 89.51 90 top
J35  HEADER 2  [HEADER_2X1]  60.04 46.39 270 top
J36  HEADER 2  [HEADER_2X1]  136.44 153.9 90 top
J37  HEADER 2  [HEADER_2X1]  151.99 157.71 270 top
J38  HEADER 2  [HEADER_2X1]  111.67 91.99 270 top
J39  HEADER 2  [HEADER_2X1]  130.72 138.02 0 top
J40  USB_MicroAB  [ZX62-AB-5PA]  4.1 99.48 270 top
J41  HEADER 2  [HEADER_2X1]  119.16 38.01 0 top
L2  2.2uH  [VLCF5020T]  84.11 43.73 90 top
L3  2.2uH  [VLCF5020T]  81.32 34.71 180 top
L4  2.2uH  [VLCF5020T]  97.07 32.42 0 top
L5  ACM2012  [ACM2012H]  132.12 159.4 90 top
L6  ACM2012  [ACM2012H]  147.67 158.53 90 top
L7  4.7uH  [CHKFOOTPRINT]  27.47 61.51 180 top
L8  4.7uH  [CHKFOOTPRINT]  91.1 40.55 0 top
L9  4.7uH  [SMD_SLF7055T]  156.12 151.55 180 top
NOREF  -  []  117.45 26.39 0 top
NOREF#2  -  [unnamed#2]  6.17 165.1 90 top
NOREF#3  -  []  170 0 90 top
NOREF#4  -  []  51.98 39.79 0 top
NOREF#5  -  [unnamed#2]  28.87 143.67 0 top
NOREF#6  -  []  0 170 0 top
NOREF#7  -  [unnamed#2]  163.65 10.16 90 top
NOREF#8  -  [unnamed#2]  6.17 33.02 90 top
NOREF#9  -  [unnamed#2]  163.65 165.1 90 top
Q1  BSS138  [SOT23-3]  34.71 164.5 90 top
Q2  BSS138  [SOT23-3]  30.26 164.38 90 top
Q3  BSS138  [SOT23-3]  25.82 164.38 90 top
Q4  BSS138  [SOT23-3]  21.37 164.38 90 top
Q5  BSS84  [SOT23-3]  127.55 160.95 270 top
R2  0  [SM-7351-RES-0402]  61.99 102.58 90 bottom
R3  0  [SM-7351-RES-0402]  58.33 102.4 0 top
R4  100K  [SM-7351-RES-0402]  60.74 100.11 270 bottom
R5  0  [SM-7351-RES-0402]  69.89 79.41 180 top
R6  10K  [SM-7351-RES-0402]  24.68 87.92 0 bottom
R7  1M  [SM-7351-RES-0402]  100.88 81.98 270 top
R8  0  [SM-7351-RES-0402]  100.88 84.06 270 top
R9  0  [SM-7351-RES-0402]  70.01 99.99 270 top
R10  0  [SM-7351-RES-0402]  69.13 88.49 0 top
R22  49.9  [SM-7351-RES-0402]  83.1 75.16 90 bottom
R23  124K  [SM-7351-RES-0402]  130.06 161.23 90 top
R30  0  [SM-7351-RES-0402]  66.84 89.19 0 top
R32  0.05ohm1% Sense  [SM_RES_LVK12]  68.24 47.15 270 top
R45  0  [SM-7351-RES-0402]  64.93 84.24 270 top
R46  0.05ohm1% Sense  [SM_RES_LVK12]  71.98 35.47 270 top
R48  10K  [SM-7351-RES-0402]  71.03 77.7 90 top
R50  150  [SM-7351-RES-0402]  84.11 18.71 90 top
R51  0  [SM-7351-RES-0402]  66.84 83.48 180 top
R53  0  [SM-7351-RES-0402]  92.75 39.66 90 bottom
R54  10K  [SM-7351-RES-0402]  83.1 36.61 0 bottom
R55  0  [SM-7351-RES-0402]  131.23 94.78 90 top
R56  0  [SM-7351-RES-0402]  69.51 93.26 90 top
R57  0  [SM-7351-RES-0402]  83.1 35.47 180 bottom
R58  0  [SM-7351-RES-0402]  145.33 71.79 0 top
R59  0  [SM-7351-RES-0402]  145.33 70.52 0 top
R60  0  [SM-7351-RES-0402]  93.51 37.5 90 bottom
R61  0  [SM-7351-RES-0402]  79.79 103.16 90 top
R62  0  [SM-7351-RES-0402]  79.16 99.73 0 top
R63  0  [SM-7351-RES-0402]  87.79 41.44 90 bottom
R64  0  [SM-7351-RES-0402]  91.86 35.6 270 bottom
R65  0  [SM-7351-RES-0402]  83.86 39.28 180 bottom
R66  0  [SM-7351-RES-0402]  81.27 101.69 0 top
R67  0  [SM-7351-RES-0402]  84.87 33.57 180 bottom
R68  0  [SM-7351-RES-0402]  107.61 46.39 90 bottom
R69  1K  [SM-7351-RES-0402]  94.02 23.53 180 top
R70  4.7K  [SM-7351-RES-0402]  29.88 89.19 180 bottom
R71  4.7K  [SM-7351-RES-0402]  23.53 89.19 0 bottom
R72  10K  [SM-7351-RES-0402]  139.74 70.4 270 bottom
R73  0  [SM-7351-RES-0402]  30.01 95.54 0 bottom
R74  0  [SM-7351-RES-0402]  23.53 91.73 0 bottom
R75  0  [SM-7351-RES-0402]  23.53 90.46 0 bottom
R76  0  [SM-7351-RES-0402]  66.71 94.53 90 top
R77  0  [SM-7351-RES-0402]  64.43 92.11 270 top
R78  0  [SM-7351-RES-0402]  71.28 91.73 90 top
R79  4.7K  [SM-7351-RES-0402]  30.01 96.81 0 bottom
R80  150  [SM-7351-RES-0402]  35.09 167.17 180 bottom
R81  150  [SM-7351-RES-0402]  30.77 167.04 180 bottom
R82  150  [SM-7351-RES-0402]  26.33 167.04 180 bottom
R83  150  [SM-7351-RES-0402]  22.01 167.04 180 bottom
R84  0  [SM-7351-RES-0402]  75.73 104.18 180 top
R85  0  [SM-7351-RES-0402]  85.51 155.61 180 top
R86  100K  [SM-7351-RES-0402]  35.72 161.58 90 top
R87  0  [SM-7351-RES-0402]  76.75 100.49 180 top
R88  0  [SM-7351-RES-0402]  77.89 105.96 90 top
R89  0  [SM-7351-RES-0402]  72.17 99.73 0 top
R90  0  [SM-7351-RES-0402]  72.17 102.27 0 top
R91  0  [SM-7351-RES-0402]  74.33 97.32 0 top
R92  0  [SM-7351-RES-0402]  46.9 115.1 270 top
R93  100K  [SM-7351-RES-0402]  31.28 161.45 90 top
R94  100K  [SM-7351-RES-0402]  22.39 161.45 90 top
R95  100K  [SM-7351-RES-0402]  26.83 161.45 90 top
R96  100K  [SM-7351-RES-0402]  164.12 69.13 0 bottom
R97  100K  [SM-7351-RES-0402]  164.12 66.59 0 bottom
R98  100K  [SM-7351-RES-0402]  164.12 64.05 0 bottom
R99  100K  [SM-7351-RES-0402]  164.12 61.51 0 bottom
R100  100K  [SM-7351-RES-0402]  164.12 58.97 0 bottom
R101  100K  [SM-7351-RES-0402]  164.12 56.43 0 bottom
R102  100K  [SM-7351-RES-0402]  164.12 53.89 0 bottom
R103  100K  [SM-7351-RES-0402]  164.12 51.35 0 bottom
R104  100K  [SM-7351-RES-0402]  164.12 91.73 0 bottom
R105  100K  [SM-7351-RES-0402]  164.12 89.19 0 bottom
R106  100K  [SM-7351-RES-0402]  164.12 86.65 0 bottom
R107  100K  [SM-7351-RES-0402]  164.12 84.11 0 bottom
R108  100K  [SM-7351-RES-0402]  164.12 81.57 0 bottom
R109  100K  [SM-7351-RES-0402]  164.12 79.03 0 bottom
R110  100K  [SM-7351-RES-0402]  164.12 76.49 0 bottom
R111  100K  [SM-7351-RES-0402]  164.12 73.95 0 bottom
R112  1K  [SM-7351-RES-0402]  8.9 43.85 90 bottom
R113  0  [SM-7351-RES-0402]  6.9 46.77 270 bottom
R114  10K  [SM-7351-RES-0402]  155.49 69.13 180 bottom
R115  10K  [SM-7351-RES-0402]  155.49 66.59 180 bottom
R116  10K  [SM-7351-RES-0402]  155.49 64.05 180 bottom
R117  10K  [SM-7351-RES-0402]  155.49 61.51 180 bottom
R118  10K  [SM-7351-RES-0402]  155.49 58.97 180 bottom
R119  10K  [SM-7351-RES-0402]  155.49 56.43 180 bottom
R120  10K  [SM-7351-RES-0402]  155.49 53.89 180 bottom
R121  10K  [SM-7351-RES-0402]  155.49 51.35 180 bottom
R122  10K  [SM-7351-RES-0402]  155.49 91.73 180 bottom
R123  10K  [SM-7351-RES-0402]  155.49 89.19 180 bottom
R124  10K  [SM-7351-RES-0402]  155.49 86.65 180 bottom
R125  10K  [SM-7351-RES-0402]  155.49 84.11 180 bottom
R126  10K  [SM-7351-RES-0402]  155.49 81.57 180 bottom
R127  10K  [SM-7351-RES-0402]  155.49 79.03 180 bottom
R128  10K  [SM-7351-RES-0402]  155.49 76.49 180 bottom
R129  10K  [SM-7351-RES-0402]  155.49 73.95 180 bottom
R130  10K  [SM-7351-RES-0402]  152.95 97.32 0 bottom
R131  10K  [SM-7351-RES-0402]  146.09 97.19 180 bottom
R132  10K  [SM-7351-RES-0402]  146.6 96.05 180 bottom
R133  0  [SM-7351-RES-0402]  140.63 102.78 180 top
R134  0  [SM-7351-RES-0402]  140.63 104.18 180 top
R135  0  [SM-7351-RES-0402]  140.63 97.07 180 top
R136  0  [SM-7351-RES-0402]  140.63 95.8 180 top
R137  0  [SM-7351-RES-0402]  140.63 98.34 180 top
R138  0  [SM-7351-RES-0402]  140.63 105.57 180 top
R139  0  [SM-7351-RES-0402]  140.63 101.51 180 top
R140  0  [SM-7351-RES-0402]  140.63 106.84 180 top
R141  0  [SM-7351-RES-0402]  140.63 108.24 180 top
R142  0  [SM-7351-RES-0402]  140.63 109.64 180 top
R143  0  [SM-7351-RES-0402]  140.63 110.91 180 top
R144  0  [SM-7351-RES-0402]  140.63 112.18 180 top
R145  0  [SM-7351-RES-0402]  140.63 113.58 180 top
R146  0  [SM-7351-RES-0402]  140.63 114.97 180 top
R147  0  [SM-7351-RES-0402]  140.63 116.24 180 top
R148  0  [SM-7351-RES-0402]  106.46 93.13 270 top
R149  0  [SM-7351-RES-0402]  104.05 93.13 270 top
R150  0  [SM-7351-RES-0402]  109.51 87.29 270 top
R151  0  [SM-7351-RES-0402]  110.15 83.73 0 top
R152  0  [SM-7351-RES-0402]  112.05 87.29 270 top
R153  0  [SM-7351-RES-0402]  97.07 90.38 270 top
R154  0  [SM-7351-RES-0402]  99.86 94.27 0 top
R155  0  [SM-7351-RES-0402]  97.07 94.47 270 top
R156  0  [SM-7351-RES-0402]  7.43 44.36 0 bottom
R157  0  [SM-7351-RES-0402]  139.61 116.24 180 top
R159  0  [SM-7351-RES-0402]  139.61 114.97 180 top
R161  0  [SM-7351-RES-0402]  139.61 113.58 180 top
R163  0  [SM-7351-RES-0402]  139.61 112.18 180 top
R165  0  [SM-7351-RES-0402]  139.61 110.91 180 top
R167  0  [SM-7351-RES-0402]  139.61 109.64 180 top
R169  0  [SM-7351-RES-0402]  139.61 108.24 180 top
R171  0  [SM-7351-RES-0402]  139.61 106.84 180 top
R173  0  [SM-7351-RES-0402]  100.88 92.75 0 top
R175  0  [SM-7351-RES-0402]  99.71 89.09 270 top
R176  0  [SM-7351-RES-0402]  131.23 95.8 270 top
R177  0  [SM-7351-RES-0402]  69.51 94.27 90 top
R178  0  [SM-7351-RES-0402]  130.85 93.89 0 bottom
R179  0  [SM-7351-RES-0402]  139.61 102.78 0 top
R180  0  [SM-7351-RES-0402]  139.61 101.51 0 top
R181  0  [SM-7351-RES-0402]  118.53 95.03 180 top
R182  0  [SM-7351-RES-0402]  139.61 98.34 0 top
R183  0  [SM-7351-RES-0402]  139.61 97.07 0 top
R184  0  [SM-7351-RES-0402]  139.61 95.8 0 top
R186  0  [SM-7351-RES-0402]  96.43 141.9 90 top
R187  0  [SM-7351-RES-0402]  93.89 141.9 90 bottom
R188  22  [SM-7351-RES-0402]  93.89 134.4 90 bottom
R189  0  [SM-7351-RES-0402]  139.61 104.18 0 top
R191  0  [SM-7351-RES-0402]  139.61 105.57 0 top
R193  0  [SM-7351-RES-0402]  114.34 155.1 90 top
R194  0  [SM-7351-RES-0402]  87.03 131.99 0 top
R196  0  [SM-7351-RES-0402]  91.73 128.18 0 top
R197  0  [SM-7351-RES-0402]  83.6 143.04 90 bottom
R198  0  [SM-7351-RES-0402]  91.73 129.2 0 top
R199  0  [SM-7351-RES-0402]  82.46 123.35 90 bottom
R200  0  [SM-7351-RES-0402]  81.19 143.04 90 bottom
R201  0  [SM-7351-RES-0402]  71.03 94.27 180 top
R202  0  [SM-7351-RES-0402]  91.73 127.04 0 top
R203  0  [SM-7351-RES-0402]  79.92 123.35 90 bottom
R204  0  [SM-7351-RES-0402]  78.65 142.94 90 bottom
R205  0  [SM-7351-RES-0402]  79.16 134.28 180 top
R206  0  [SM-7351-RES-0402]  102.91 155.1 90 top
R207  0  [SM-7351-RES-0402]  76.11 141.9 90 bottom
R208  0  [SM-7351-RES-0402]  71.28 92.75 90 top
R209  0  [SM-7351-RES-0402]  100.37 155.23 90 top
R210  0  [SM-7351-RES-0402]  73.57 133.51 90 top
R211  0  [SM-7351-RES-0402]  84.49 155.61 180 top
R212  0  [SM-7351-RES-0402]  71.03 142.94 90 bottom
R213  0  [SM-7351-RES-0402]  79.79 104.18 90 top
R214  0  [SM-7351-RES-0402]  97.45 155.23 90 top
R215  0  [SM-7351-RES-0402]  68.49 142.94 90 bottom
R216  0  [SM-7351-RES-0402]  80.17 99.73 0 top
R217  0  [SM-7351-RES-0402]  94.27 155.23 90 top
R218  0  [SM-7351-RES-0402]  77.89 106.97 270 top
R219  0  [SM-7351-RES-0402]  66.97 142.89 90 bottom
R220  0  [SM-7351-RES-0402]  80.68 98.08 0 top
R221  0  [SM-7351-RES-0402]  66.71 95.54 270 top
R222  0  [SM-7351-RES-0402]  72.55 97.83 90 top
R223  0  [SM-7351-RES-0402]  90.08 155.23 90 top
R224  0  [SM-7351-RES-0402]  73.19 102.27 180 top
R225  0  [SM-7351-RES-0402]  74.71 104.18 180 top
R226  0  [SM-7351-RES-0402]  59.6 130.72 90 bottom
R227  0  [SM-7351-RES-0402]  51.35 127.29 180 top
R228  0  [SM-7351-RES-0402]  64.93 91.6 180 top
R229  0  [SM-7351-RES-0402]  75.73 100.49 180 top
R230  0  [SM-7351-RES-0402]  140.25 153.58 270 top
R231  22  [SM-7351-RES-0402]  81.77 101.18 90 top
R232  0  [SM-7351-RES-0402]  73.19 99.73 0 top
R233  0  [SM-7351-RES-0402]  54.52 130.47 90 bottom
R234  0  [SM-7351-RES-0402]  46.39 114.59 0 top
R235  22  [SM-7351-RES-0402]  53.25 133.64 270 top
R236  0  [SM-7351-RES-0402]  75.35 97.32 0 top
R237  22  [SM-7351-RES-0402]  83.22 105.07 90 top
R239  10K  [SM-7351-RES-0402]  128.18 79.79 180 top
R240  0  [SM-7351-RES-0402]  140.37 86.02 0 top
R241  0  [SM-7351-RES-0402]  140.37 87.03 0 top
R242  0  [SM-7351-RES-0402]  109.51 86.27 90 top
R243  0  [SM-7351-RES-0402]  110.65 83.22 90 top
R244  0  [SM-7351-RES-0402]  72.55 96.81 90 top
R245  0  [SM-7351-RES-0402]  140.37 83.6 0 top
R246  0  [SM-7351-RES-0402]  140.37 84.62 0 top
R247  0  [SM-7351-RES-0402]  97.07 89.37 90 top
R248  0  [SM-7351-RES-0402]  100.88 94.27 180 top
R249  0  [SM-7351-RES-0402]  52.23 62.01 90 top
R250  0  [SM-7351-RES-0402]  63.92 91.6 0 top
R251  0  [SM-7351-RES-0402]  140.37 81.57 0 top
R252  0  [SM-7351-RES-0402]  140.37 82.59 0 top
R253  0  [SM-7351-RES-0402]  97.07 93.46 90 top
R254  0  [SM-7351-RES-0402]  128.18 83.86 180 top
R255  0  [SM-7351-RES-0402]  73.57 132.5 90 top
R256  0  [SM-7351-RES-0402]  140.37 79.54 0 top
R257  0  [SM-7351-RES-0402]  140.37 80.56 0 top
R258  0  [SM-7351-RES-0402]  128.18 81.83 180 top
R259  0  [SM-7351-RES-0402]  128.18 82.84 180 top
R260  0  [SM-7351-RES-0402]  140.37 78.4 0 top
R261  0  [SM-7351-RES-0402]  106.46 92.11 90 top
R262  0  [SM-7351-RES-0402]  128.18 80.81 180 top
R263  0  [SM-7351-RES-0402]  104.05 92.11 90 top
R264  0  [SM-7351-RES-0402]  112.05 86.27 90 top
R265  0  [SM-7351-RES-0402]  146.34 71.79 180 top
R266  0  [SM-7351-RES-0402]  128.18 78.78 180 top
R267  0  [SM-7351-RES-0402]  140.37 77.13 0 top
R268  0  [SM-7351-RES-0402]  146.34 70.52 180 top
R269  0  [SM-7351-RES-0402]  128.18 76.75 180 top
R270  0  [SM-7351-RES-0402]  128.18 77.76 180 top
R271  0  [SM-7351-RES-0402]  140.37 74.97 0 top
R272  0  [SM-7351-RES-0402]  128.18 74.71 180 top
R273  0  [SM-7351-RES-0402]  128.18 75.73 180 top
R274  10K  [SM-7351-RES-0402]  140.37 75.98 180 top
R275  4.7K  [SM-7351-RES-0402]  144.11 4.99 270 bottom
R276  4.7K  [SM-7351-RES-0402]  145.38 4.99 270 bottom
R277  51K  [SM-7351-RES-0402]  161.96 20.87 270 top
R278  0  [SM-7351-RES-0402]  106.97 92.62 180 top
R279  0  [SM-7351-RES-0402]  110.65 84.24 270 top
R280  0  [SM-7351-RES-0402]  100.37 94.78 270 top
R281  0  [SM-7351-RES-0402]  141.39 77.13 180 top
R282  0  [SM-7351-RES-0402]  141.39 80.56 180 top
R283  0  [SM-7351-RES-0402]  127.16 81.83 0 top
R284  0  [SM-7351-RES-0402]  141.39 78.4 180 top
R285  0  [SM-7351-RES-0402]  127.16 83.86 0 top
R286  0  [SM-7351-RES-0402]  104.56 92.62 180 top
R287  0  [SM-7351-RES-0402]  112.56 86.78 180 top
R288  0  [SM-7351-RES-0402]  141.39 82.59 180 top
R289  0  [SM-7351-RES-0402]  127.16 77.76 0 top
R290  0  [SM-7351-RES-0402]  127.16 82.84 0 top
R291  0  [SM-7351-RES-0402]  127.16 80.81 0 top
R292  4.3K  [SM-7351-RES-0402]  137.32 28.61 180 bottom
R293  0  [SM-7351-RES-0402]  127.16 78.78 0 top
R294  0  [SM-7351-RES-0402]  141.39 79.54 180 top
R295  0  [SM-7351-RES-0402]  110.02 86.78 180 top
R296  0  [SM-7351-RES-0402]  103.42 155.61 180 top
R297  0  [SM-7351-RES-0402]  97.57 89.88 180 top
R298  0  [SM-7351-RES-0402]  97.57 93.97 180 top
R299  0  [SM-7351-RES-0402]  141.39 86.02 180 top
R300  0  [SM-7351-RES-0402]  141.39 87.03 180 top
R301  0  [SM-7351-RES-0402]  141.39 83.6 180 top
R302  0  [SM-7351-RES-0402]  141.39 84.62 180 top
R303  0  [SM-7351-RES-0402]  141.39 81.57 180 top
R304  10K  [SM-7351-RES-0402]  142.2 9.94 270 bottom
R305  0  [SM-7351-RES-0402]  141.39 74.97 180 top
R306  10K  [SM-7351-RES-0402]  132.19 31.43 180 top
R307  0  [SM-7351-RES-0402]  127.16 76.75 0 top
R308  0  [SM-7351-RES-0402]  160.82 20.87 90 top
R311  0  [SM-7351-RES-0402]  127.16 74.71 0 top
R312  0  [SM-7351-RES-0402]  127.16 75.73 0 top
R313  0  [SM-7351-RES-0402]  130.72 95.29 0 top
R314  0  [SM-7351-RES-0402]  69 93.76 0 top
R315  0  [SM-7351-RES-0402]  64.43 91.1 90 top
R316  0  [SM-7351-RES-0402]  53.25 132.63 90 top
R317  0  [SM-7351-RES-0402]  83.22 106.08 270 top
R318  0  [SM-7351-RES-0402]  50.84 126.78 90 top
R319  0  [SM-7351-RES-0402]  46.9 114.08 90 top
R320  0  [SM-7351-RES-0402]  82.28 101.69 180 top
R321  0  [SM-7351-RES-0402]  93.89 133.39 90 bottom
R322  0  [SM-7351-RES-0402]  137.45 13.37 270 bottom
R323  0  [SM-7351-RES-0402]  114.85 155.61 180 top
R324  0  [SM-7351-RES-0402]  60.84 96.4 0 top
R325  0  [SM-7351-RES-0402]  136.69 37.88 90 bottom
R326  4.7K  [SM-7351-RES-0402]  163.11 20.87 90 top
R327  0  [SM-7351-RES-0402]  6.13 110.02 180 bottom
R328  0  [SM-7351-RES-0402]  85 155.1 270 top
R329  10K  [SM-7351-RES-0402]  6.13 123.74 180 bottom
R330  10K  [SM-7351-RES-0402]  6.13 121.45 180 bottom
R331  10K  [SM-7351-RES-0402]  6.13 118.02 180 bottom
R332  10K  [SM-7351-RES-0402]  6.13 116.88 180 bottom
R333  10K  [SM-7351-RES-0402]  6.13 114.59 180 bottom
R334  10K  [SM-7351-RES-0402]  6.13 112.31 180 bottom
R335  0  [SM-7351-RES-0402]  81.95 122.59 180 top
R336  0  [SM-7351-RES-0402]  72.68 102.78 90 top
R337  0  [SM-7351-RES-0402]  14.13 119.04 180 bottom
R338  0  [SM-7351-RES-0402]  6.13 124.88 180 bottom
R339  0  [SM-7351-RES-0402]  6.13 126.02 180 bottom
R340  0  [SM-7351-RES-0402]  6.13 127.16 180 bottom
R341  0  [SM-7351-RES-0402]  6.13 128.31 180 bottom
R342  0  [SM-7351-RES-0402]  6.26 132.63 180 bottom
R343  0  [SM-7351-RES-0402]  6.26 133.77 180 bottom
R344  0  [SM-7351-RES-0402]  6.26 134.91 180 bottom
R345  0  [SM-7351-RES-0402]  6.26 136.05 180 bottom
R346  0  [SM-7351-RES-0402]  86.02 131.99 180 top
R347  0  [SM-7351-RES-0402]  28.99 124.75 180 top
R348  0  [SM-7351-RES-0402]  50.33 127.29 180 top
R349  0  [SM-7351-RES-0402]  66.2 95.03 180 top
R350  0  [SM-7351-RES-0402]  113.83 155.61 180 top
R351  0  [SM-7351-RES-0402]  63.66 97.07 90 bottom
R352  0  [SM-7351-RES-0402]  47.41 114.59 0 top
R353  0  [SM-7351-RES-0402]  20.61 139.1 0 bottom
R354  0  [SM-7351-RES-0402]  74.84 97.83 90 top
R355  0  [SM-7351-RES-0402]  76.24 99.99 270 top
R356  0  [SM-7351-RES-0402]  72.68 100.24 90 top
R357  0  [SM-7351-RES-0402]  75.22 103.67 270 top
R358  0  [SM-7351-RES-0402]  13.88 149.77 90 top
R359  57.6K  [SM-7351-RES-0402]  13.88 154.6 270 top
R360  30.1K  [SM-7351-RES-0402]  17.06 155.1 180 top
R361  0  [SM-7351-RES-0402]  72.05 97.32 0 top
R362  0  [SM-7351-RES-0402]  79.67 100.24 270 top
R363  0  [SM-7351-RES-0402]  79.67 98.08 0 top
R364  0  [SM-7351-RES-0402]  79.29 103.67 0 top
R365  10K  [SM-7351-RES-0402]  46.39 148.37 90 bottom
R366  10K  [SM-7351-RES-0402]  48.55 148.37 90 bottom
R367  10K  [SM-7351-RES-0402]  50.84 148.37 90 bottom
R368  10K  [SM-7351-RES-0402]  49.69 148.37 90 bottom
R369  10K  [SM-7351-RES-0402]  43.85 148.37 90 bottom
R370  10K  [SM-7351-RES-0402]  47.66 165.77 90 bottom
R371  10K  [SM-7351-RES-0402]  50.08 165.77 90 bottom
R372  10K  [SM-7351-RES-0402]  57.57 165.77 90 bottom
R373  10K  [SM-7351-RES-0402]  60.11 165.77 90 bottom
R378  470K  [SM-7351-RES-0402]  63.16 144.69 90 top
R379  0  [SM-7351-RES-0402]  77.38 106.46 0 top
R380  0  [SM-7351-RES-0402]  72.3 91.67 90 top
R381  120K  [SM-7351-RES-0402]  134.15 162.19 270 top
R382  10K  [SM-7351-RES-0402]  138.98 150.72 270 top
R383  10K  [SM-7351-RES-0402]  137.32 145.13 90 bottom
R384  0  [SM-7351-RES-0402]  140.25 152.63 270 top
R385  0  [SM-7351-RES-0402]  149.77 161.52 270 top
R386  100K  [SM-7351-RES-0402]  156.88 144.18 270 top
R387  10K  [SM-7351-RES-0402]  145.64 144.69 270 bottom
R388  0  [SM-7351-RES-0402]  25.06 53.38 180 bottom
R389  0  [SM-7351-RES-0402]  27.22 53.38 180 bottom
R390  220  [SM-7351-RES-0402]  22.9 5.75 270 top
R391  100K  [SM-7351-RES-0402]  27.22 58.84 180 bottom
R392  220  [SM-7351-RES-0402]  44.61 5.88 270 top
R393  10K  [SM-7351-RES-0402]  34.58 61.51 90 bottom
R394  4.7K  [SM-7351-RES-0402]  33.31 61.51 270 top
R395  22  [SM-7351-RES-0402]  35.85 52.36 0 bottom
R396  0  [SM-7351-RES-0402]  66.97 143.9 270 bottom
R397  0  [SM-7351-RES-0402]  81.19 144.06 270 bottom
R398  0  [SM-7351-RES-0402]  83.6 144.06 270 bottom
R399  0  [SM-7351-RES-0402]  78.65 143.95 270 bottom
R400  0  [SM-7351-RES-0402]  71.03 143.95 270 bottom
R401  0  [SM-7351-RES-0402]  68.49 143.95 270 bottom
R402  0  [SM-7351-RES-0402]  129.45 163.87 180 top
R404  0  [SM-7351-RES-0402]  81.77 102.2 270 top
R405  0  [SM-7351-RES-0402]  34.58 61.51 90 top
R406  2.37K  [SM-7351-RES-0402]  30.77 55.66 180 bottom
R407  10K  [SM-7351-RES-0402]  27.22 59.98 0 bottom
R408  1.5K  [SM-7351-RES-0402]  30.39 61 180 bottom
R409  10K  [SM-7351-RES-0402]  25.06 58.84 180 bottom
R410  0  [SM-7351-RES-0402]  94.4 133.9 0 bottom
R411  10K  [SM-7351-RES-0402]  39.6 55.54 0 top
R412  10K  [SM-7351-RES-0402]  146.91 152.63 270 top
R413  10K  [SM-7351-RES-0402]  39.6 54.27 0 top
R414  10K  [SM-7351-RES-0402]  39.6 56.81 0 top
R415  22  [SM-7351-RES-0402]  86.88 101.69 270 bottom
R416  22  [SM-7351-RES-0402]  86.19 97.95 270 top
R417  22  [SM-7351-RES-0402]  88.49 97.95 270 top
R418  22  [SM-7351-RES-0402]  89.45 97.95 270 top
R419  10K  [SM-7351-RES-0402]  39.6 53 0 top
R420  22  [SM-7351-RES-0402]  84.29 97.95 270 top
R421  22  [SM-7351-RES-0402]  85.24 97.95 270 top
R422  10K  [SM-7351-RES-0402]  39.6 58.08 0 top
R423  0  [SM-7351-RES-0402]  41.53 58.08 0 top
R424  0  [SM-7351-RES-0402]  41.53 55.54 0 top
R425  0  [SM-7351-RES-0402]  41.53 54.27 0 top
R426  10K  [SM-7351-RES-0402]  39.6 51.73 0 top
R427  0  [SM-7351-RES-0402]  41.53 53 0 top
R428  0  [SM-7351-RES-0402]  41.53 51.73 0 top
R430  0  [SM-7351-RES-0402]  41.53 56.81 0 top
R431  10K  [SM-7351-RES-0402]  38.77 48.04 90 bottom
R432  22  [SM-7351-RES-0402]  81.7 108.11 0 top
R433  22  [SM-7351-RES-0402]  91.1 97.95 270 top
R434  22  [SM-7351-RES-0402]  92.87 100.37 270 top
R435  10K  [SM-7351-RES-0402]  37.5 48.04 90 bottom
R436  0  [SM-7351-RES-0402]  80.17 134.28 0 top
R437  0  [SM-7351-RES-0402]  114.34 156.12 270 top
R438  0  [SM-7351-RES-0402]  72.05 94.27 0 top
R439  0  [SM-7351-RES-0402]  104.05 97.38 270 bottom
R440  0  [SM-7351-RES-0402]  102.78 97.38 270 bottom
R441  0  [SM-7351-RES-0402]  105.32 97.38 270 bottom
R442  0  [SM-7351-RES-0402]  102.91 156.12 270 top
R443  0  [SM-7351-RES-0402]  76.24 101 90 top
R444  0  [SM-7351-RES-0402]  100.37 156.25 270 top
R445  0  [SM-7351-RES-0402]  75.22 104.69 90 top
R446  0  [SM-7351-RES-0402]  97.45 156.25 270 top
R447  0  [SM-7351-RES-0402]  94.27 156.25 270 top
R448  0  [SM-7351-RES-0402]  86.52 131.48 270 top
R449  0  [SM-7351-RES-0402]  82.97 122.59 0 top
R450  0  [SM-7351-RES-0402]  90.08 156.25 270 top
R451  0  [SM-7351-RES-0402]  87.54 156.25 90 top
R452  0  [SM-7351-RES-0402]  85 156.12 90 top
R453  4.7K  [SM-7351-RES-0402]  73.57 40.93 270 bottom
R454  4.7K  [SM-7351-RES-0402]  71.03 40.8 270 bottom
R455  10K  [SM-7351-RES-0402]  65.95 40.55 270 bottom
R456  0  [SM-7351-RES-0402]  104.05 96.37 90 bottom
R457  0  [SM-7351-RES-0402]  102.78 96.37 90 bottom
R458  0  [SM-7351-RES-0402]  105.32 96.37 90 bottom
R459  0  [SM-7351-RES-0402]  18.83 108.88 180 top
R460  0  [SM-7351-RES-0402]  22.77 113.07 90 top
R461  100  [SM-7351-RES-0402]  68.87 83.98 270 bottom
R462  100  [SM-7351-RES-0402]  64.43 86.78 270 bottom
R463  0  [SM-7351-RES-0603]  96.05 26.45 180 top
R464  0  [SM-7351-RES-0603]  90.97 26.71 90 bottom
R465  0  [SM-7351-RES-0603]  99.48 27.22 180 top
R466  0  [SM-7351-RES-0603]  96.05 28.1 0 top
R467  0  [SM-7351-RES-0603]  102.91 27.22 180 top
R468  0  [SM-7351-RES-0603]  77.25 36.11 270 top
R469  0  [SM-7351-RES-0603]  80.17 42.96 270 top
R470  0  [SM-7351-RES-0603]  92.49 44.49 270 top
R471  0  [SM-7351-RES-0603]  97.83 36.11 0 top
R472  0  [SM-7351-RES-0603]  117.51 47.92 90 bottom
R473  0  [SM-7351-RES-0603]  97.83 37.88 0 top
R474  0  [SM-7351-RES-0603]  82.71 30.77 180 top
R475  0  [SM-7351-RES-0603]  82.71 29.25 180 top
R476  0  [SM-7351-RES-0603]  90.46 27.47 180 top
R477  0  [SM-7351-RES-0603]  82.71 27.72 0 top
R478  0  [SM-7351-RES-0402]  146.6 20.23 90 bottom
R479  0  [SM-7351-RES-0402]  35.6 61.51 90 top
R485  0  [SM-7351-RES-0402]  6.13 111.16 0 bottom
R486  0  [SM-7351-RES-0402]  6.13 113.45 0 bottom
R487  0  [SM-7351-RES-0402]  6.13 115.73 0 bottom
R488  0  [SM-7351-RES-0402]  6.13 119.16 0 bottom
R489  0  [SM-7351-RES-0402]  6.13 120.31 0 bottom
R490  0  [SM-7351-RES-0402]  6.13 122.59 0 bottom
R491  0  [SM-7351-RES-0402]  23.91 113.07 90 top
R492  0  [SM-7351-RES-0402]  17.82 108.88 180 top
R493  0.24ohm1% Sense  [SM_RES_0805_KELV]  120.81 69.51 180 bottom
R494  0.24ohm1% Sense  [SM_RES_0805_KELV]  134.78 131.86 270 bottom
R495  0.24ohm1% Sense  [SM_RES_0805_KELV]  101.76 141.26 0 bottom
R496  0.24ohm1% Sense  [SM_RES_0805_KELV]  51.66 86.91 0 bottom
R497  2ohm1% Sense  [SM_RES_0805_KELV]  95.67 115.73 180 top
R498  0.24ohm1% Sense  [SM_RES_0805_KELV]  101.89 115.48 0 bottom
R499  2ohm1% Sense  [SM_RES_0805_KELV]  48.68 96.18 90 bottom
R500  2ohm1% Sense  [SM_RES_0805_KELV]  48.68 101.89 90 bottom
R501  1ohm1% Sense  [SM_RES_0805_KELV]  47.92 75.73 90 bottom
R502  1ohm1% Sense  [SM_RES_0805_KELV]  115.99 141.13 180 top
R503  2ohm1% Sense  [SM_RES_0805_KELV]  106.21 63.79 180 bottom
R504  2ohm1% Sense  [SM_RES_0805_KELV]  108.88 141.13 180 top
R505  2ohm1% Sense  [SM_RES_0805_KELV]  61.31 49.31 180 bottom
R506  2ohm1% Sense  [SM_RES_0805_KELV]  113.45 63.79 180 bottom
R507  2ohm1% Sense  [SM_RES_0805_KELV]  61.25 55.03 180 bottom
R508  0.24ohm1% Sense  [SM_RES_0805_KELV]  113.26 69.44 0 top
R509  0  [SM-7351-RES-0402]  99.86 155.74 0 top
R510  0  [SM-7351-RES-0402]  93.76 155.74 0 top
R511  0  [SM-7351-RES-0402]  89.57 155.74 0 top
R512  0  [SM-7351-RES-0402]  59.6 131.74 270 bottom
R513  0.24ohm1% Sense  [SM_RES_0805_KELV]  116.37 39.15 90 top
R515  10K  [SM-7351-RES-0402]  27.47 111.67 0 top
R516  0  [SM-7351-RES-0402]  27.47 110.53 180 top
R517  100  [SM-7351-RES-0402]  20.48 87.41 270 top
R518  10K  [SM-7351-RES-0402]  29.37 137.83 270 bottom
R519  10K  [SM-7351-RES-0402]  18.2 118.02 270 bottom
R520  1.62M  [SM-7351-RES-0402]  153.07 145.2 180 top
R521  180K  [SM-7351-RES-0402]  153.07 144.18 0 top
R541  2.2K  [SM-7351-RES-0402]  85 78.75 90 bottom
R542  2.2K  [SM-7351-RES-0402]  85.05 72.78 180 bottom
R544  10K  [SM-7351-RES-0402]  59.28 35.47 180 top
R545  0.24ohm1% Sense  [SM_RES_0805_KELV]  112.94 94.84 180 bottom
R546  0.24ohm1% Sense  [SM_RES_0805_KELV]  133.58 139.29 270 top
R547  4.7K  [SM-7351-RES-0402]  78.52 97.57 90 bottom
R548  4.7K  [SM-7351-RES-0402]  77.38 97.57 90 bottom
R550  0  [SM-7351-RES-0402]  83.22 26.2 180 bottom
R551  0  [SM-7351-RES-0402]  83.22 25.06 180 bottom
R552  4.7K  [SM-7351-RES-0402]  72.17 96.68 90 bottom
R553  4.7K  [SM-7351-RES-0402]  71.03 96.68 90 bottom
R554  4.7K  [SM-7351-RES-0402]  77.76 101.13 90 bottom
R555  4.7K  [SM-7351-RES-0402]  78.9 101.13 90 bottom
R556  0  [SM-7351-RES-0402]  85.51 31.79 0 bottom
R557  0  [SM-7351-RES-0603]  84.11 25.31 180 top
R558  0  [SM-7351-RES-0603]  153.33 160.44 0 top
R559  0  [SM-7351-RES-0402]  10.83 46.9 90 bottom
R560  0  [SM-7351-RES-0402]  9.05 46.39 0 bottom
R561  0  [SM-7351-RES-0402]  73.32 78.27 180 top
R562  0  [SM-7351-RES-0402]  88.81 40.55 270 top
R563  1.2K, 1/4W  [SM-7351-RES-0805]  96.3 98.46 270 top
R564  1.2K, 1/4W  [SM-7351-RES-0805]  90.59 104.05 270 top
R565  10K  [SM-7351-RES-0402]  125.26 161.07 270 top
R566  0  [SM-7351-RES-0402]  125.26 163.49 90 top
R567  2.2K  [SM-7351-RES-0402]  132.19 32.55 180 top
R568  2.2K  [SM-7351-RES-0402]  132.19 33.84 180 top
R569  10K  [SM-7351-RES-0402]  132.22 28.51 0 top
R570  10K  [SM-7351-RES-0402]  132.17 30.29 180 top
R571  0  [SM-7351-RES-0402]  130.06 159.02 90 top
R572  240  [SM-7351-RES-0402]  92.24 55.79 0 bottom
R573  240  [SM-7351-RES-0402]  77.63 55.79 0 bottom
R575  0  [SM-7351-RES-0402]  13.88 52.36 180 top
R576  0  [SM-7351-RES-0402]  9.18 68.49 90 top
R577  0  [SM-7351-RES-0402]  10.2 68.49 90 top
R578  0  [SM-7351-RES-0402]  11.21 68.49 90 top
R579  0  [SM-7351-RES-0402]  12.23 68.49 90 top
R580  0  [SM-7351-RES-0402]  13.25 68.49 90 top
R581  0  [SM-7351-RES-0402]  15.53 68.49 90 top
R582  0  [SM-7351-RES-0402]  14.26 68.49 90 top
R583  0  [SM-7351-RES-0402]  17.56 68.49 90 top
R584  12K, 1%  [SM-7351-RES-0402]  12.61 79.54 0 bottom
